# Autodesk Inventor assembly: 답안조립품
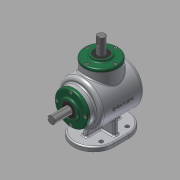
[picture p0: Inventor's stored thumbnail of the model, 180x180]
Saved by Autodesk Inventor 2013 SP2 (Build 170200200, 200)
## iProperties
Created: 2023-01
Part Number: 답안조립품
Document SubType Name: Assembly
Designer: aa
Author: aa
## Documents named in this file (14)
- C:\Users\aa\Desktop\730106V1025\답안조립품.iam
- C:\Users\aa\Desktop\730106V1025\본체.ipt
- C:\Users\aa\Desktop\730106V1025\M4.ipt
- C:\Users\aa\Desktop\730106V1025\메인 베벨기어.ipt
- C:\Users\aa\Desktop\730106V1025\메인 축.ipt
- 메인 축.ipt
- C:\Users\aa\Desktop\730106V1025\베어링 6203.ipt
- C:\Users\aa\Desktop\730106V1025\서브 베벨기어.ipt
- C:\Users\aa\Desktop\730106V1025\서브 축.ipt
- 서브 축.ipt
- C:\Users\aa\Desktop\730106V1025\오일실 17 32 8.ipt
- C:\Users\aa\Desktop\730106V1025\커버.ipt
- C:\Users\aa\Desktop\730106V1025\키 4x4.ipt
- C:\Users\aa\Desktop\730106V1025\키 5x5.ipt
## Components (8 placed, 1 different names)
1. M4:1
2. M4:3
3. M4:4
4. M4:5
5. M4:2
6. M4:6
7. M4:7
8. M4:8
